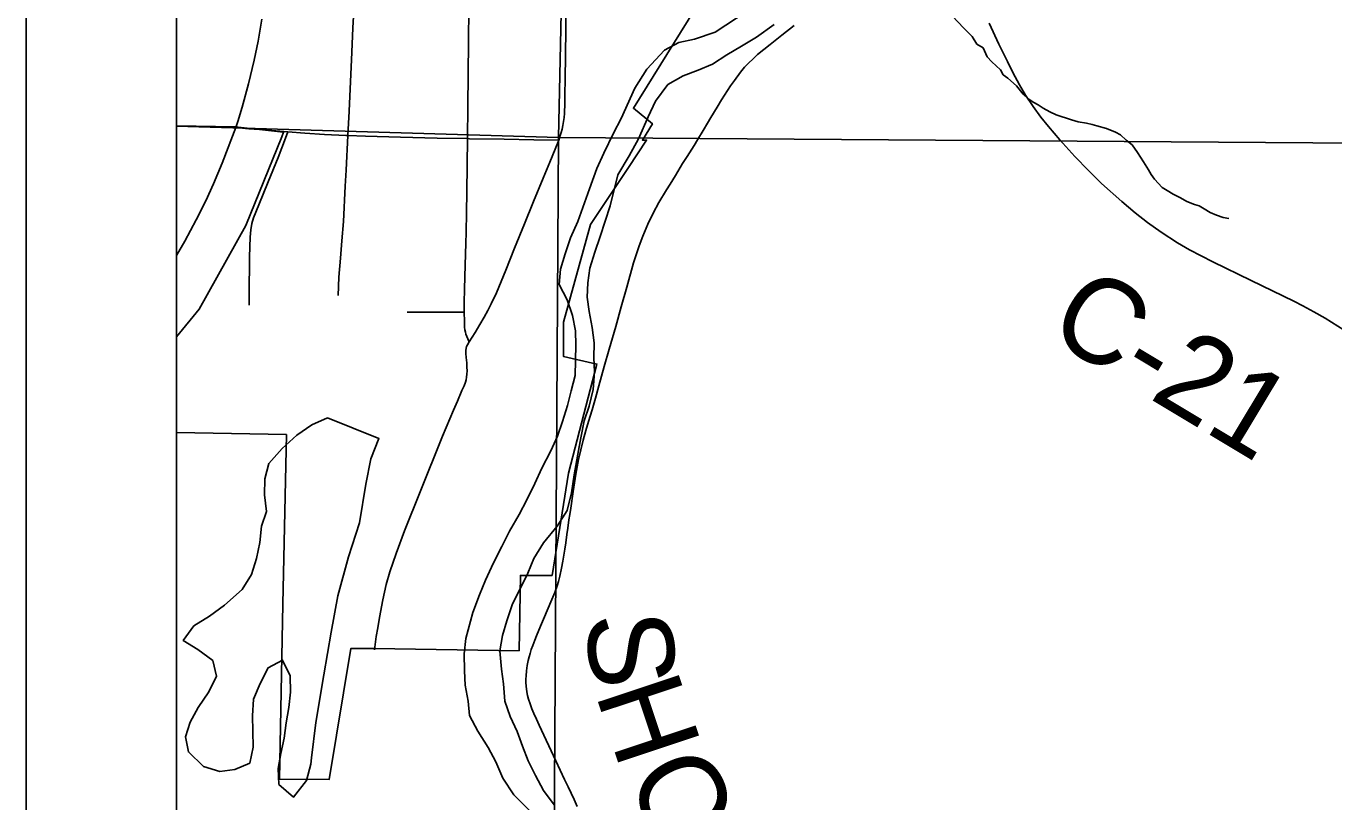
# Model space of a CAD drawing. Extents: x -8.8 to 41.4, y 0 to 34.6.
# Drawn here: x -8.774 to -7.904, y 16.161 to 16.678 of the extents above; entities that cross this region are included whole.
import ezdxf

# ---------------------------------------------------------------- set-up
doc = ezdxf.new("R2010")
doc.units = 0
for name, color, linetype in [('GM_X_City_Street', 7, 'Continuous'), ('GM_X_Corporation', 7, 'Continuous'), ('GM_X_County_Road', 7, 'Continuous'), ('GM_X_Major_Lake', 7, 'Continuous'), ('GM_X_Minor_River', 7, 'Continuous'), ('GM_X_Township_Road_Text', 7, 'Continuous'), ('GM_X_US_Route', 7, 'Continuous'), ('SH_Border', 7, 'Continuous')]:
    doc.layers.add(name, color=color, linetype=linetype)

msp = doc.modelspace()

# ---------------------------------------------------------------- linework, layer by layer
at = {"layer": 'GM_X_City_Street'}
for points in [[(-8.5667, 16.49846), (-8.56617, 16.51081), (-8.56514, 16.52326), (-8.56417, 16.53491), (-8.5631, 16.54775), (-8.56186, 16.5713), (-8.56129, 16.58184), (-8.56017, 16.60505), (-8.55938, 16.62117), (-8.55748, 16.6605), (-8.55678, 16.67663), (-8.55607, 16.69151), (-8.55316, 16.72915), (-8.5527, 16.73735), (-8.5517, 16.75531), (-8.54759, 16.82863), (-8.54694, 16.84339), (-8.54679, 16.84674)], [(-8.48719, 16.42822), (-8.4842, 16.43521), (-8.48281, 16.43844), (-8.48179, 16.44092), (-8.48135, 16.44244), (-8.4811, 16.44421), (-8.48091, 16.44618), (-8.48084, 16.4484), (-8.48091, 16.4508), (-8.48104, 16.45378), (-8.48133, 16.45726), (-8.48155, 16.4598), (-8.48155, 16.46195), (-8.48141, 16.46335), (-8.4811, 16.46449), (-8.48046, 16.46576), (-8.47946, 16.46765), (-8.47546, 16.47393), (-8.47235, 16.4792), (-8.46943, 16.48401), (-8.4669, 16.48858), (-8.46468, 16.49302), (-8.46131, 16.50025), (-8.45508, 16.51545), (-8.44925, 16.52995), (-8.44264, 16.54625), (-8.43665, 16.56106), (-8.43023, 16.57657), (-8.42574, 16.58737), (-8.42222, 16.59584), (-8.41984, 16.60189), (-8.41905, 16.60435), (-8.41822, 16.60693), (-8.41755, 16.60935), (-8.41697, 16.61177), (-8.41657, 16.61425), (-8.41622, 16.61694), (-8.41599, 16.61972), (-8.41572, 16.62645), (-8.41564, 16.63273), (-8.41554, 16.64203), (-8.41488, 16.69208)], [(-8.47946, 16.46765), (-8.48033, 16.46959), (-8.48097, 16.47121), (-8.48157, 16.47271), (-8.48196, 16.47412), (-8.48225, 16.47574), (-8.48246, 16.47745), (-8.48255, 16.47899), (-8.48264, 16.48129), (-8.48281, 16.4874), (-8.48272, 16.49359), (-8.48246, 16.50299), (-8.48202, 16.51872), (-8.48169, 16.5333), (-8.48152, 16.54053), (-8.4813, 16.55377), (-8.48107, 16.56738), (-8.48061, 16.60292), (-8.4803, 16.62437), (-8.47981, 16.66741), (-8.47966, 16.69004)], [(-8.63483, 16.61028), (-8.63241, 16.61007), (-8.62609, 16.60955), (-8.61907, 16.60896), (-8.60548, 16.60784), (-8.60008, 16.60739), (-8.58883, 16.60662), (-8.57576, 16.60578), (-8.56158, 16.6051), (-8.56017, 16.60505), (-8.54838, 16.60466), (-8.52509, 16.60389), (-8.50078, 16.60335), (-8.48061, 16.60292), (-8.47911, 16.60288), (-8.45617, 16.60252), (-8.4363, 16.60224), (-8.41984, 16.60189)], [(-8.62591, 16.49199), (-8.62592, 16.49882), (-8.6257, 16.52428), (-8.62527, 16.53733), (-8.62478, 16.54227), (-8.62398, 16.54654), (-8.62293, 16.55011), (-8.61953, 16.55878), (-8.61312, 16.57428), (-8.60647, 16.59035), (-8.60167, 16.60314), (-8.60008, 16.60739)], [(-8.5206, 16.48748), (-8.51286, 16.48747), (-8.50132, 16.48747), (-8.48992, 16.48746), (-8.48281, 16.4874)]]:
    msp.add_lwpolyline(points, dxfattribs=at)
at = {"layer": 'GM_X_Corporation'}
for points in [[(-8.6743, 18.69247), (-8.6743, 14.09996), (-5.44416, 14.09996), (-5.44317, 14.22654), (-5.4429, 14.26177), (-5.44035, 14.58818), (-5.43679, 15.04456), (-5.435, 15.31635), (-5.42821, 16.35067), (-5.4212, 16.54833), (-5.41292, 17.38361), (-5.40083, 18.63689)], [(-8.6743, 17.24471), (-8.6743, 16.61157), (-8.63507, 16.61081), (-8.60299, 16.60722), (-8.60422, 16.60416), (-8.62815, 16.54522), (-8.65907, 16.4894), (-8.6743, 16.47104), (-8.6743, 16.4073), (-8.60107, 16.40598), (-8.60337, 16.29312), (-8.60575, 16.17658), (-8.57266, 16.17628), (-8.5582, 16.26352), (-8.54271, 16.26348), (-8.4462, 16.26203), (-8.44534, 16.31218), (-8.42424, 16.31218), (-8.41328, 16.38015), (-8.39443, 16.45291), (-8.41674, 16.45798), (-8.41667, 16.48073), (-8.39862, 16.54582), (-8.37338, 16.58383), (-8.36135, 16.60196), (-8.36415, 16.60199), (-8.35743, 16.61288), (-8.37005, 16.62314), (-8.3024, 16.73229)]]:
    msp.add_lwpolyline(points, dxfattribs=at)
for points in [[(-8.6743, 17.6149), (-8.6743, 16.61123), (-8.42005, 16.60371), (-8.39835, 17.60863)], [(-8.39835, 17.60863), (-7.43777, 17.58688), (-7.44736, 16.59683), (-8.42005, 16.60371)], [(-8.6743, 16.61123), (-8.6743, 15.60235), (-8.42609, 15.59413), (-8.42005, 16.60371)], [(-8.42005, 16.60371), (-7.44736, 16.59683), (-7.4468, 15.57832), (-8.42609, 15.59413)]]:
    msp.add_lwpolyline(points, close=True, dxfattribs=at)
at = {"layer": 'GM_X_County_Road'}
for points in [[(-8.38957, 16.45116), (-8.38626, 16.46289), (-8.38188, 16.47778), (-8.37819, 16.49092), (-8.37453, 16.50408), (-8.36994, 16.52024), (-8.36632, 16.53151), (-8.36394, 16.53795), (-8.36053, 16.54601), (-8.35704, 16.55335), (-8.35308, 16.56043), (-8.34797, 16.56895), (-8.34571, 16.57265), (-8.34215, 16.57846), (-8.3406, 16.5811), (-8.33732, 16.58635), (-8.336, 16.58845), (-8.33433, 16.59106), (-8.3297, 16.59838), (-8.32742, 16.60206), (-8.3236, 16.60845), (-8.32075, 16.61325), (-8.31855, 16.61699), (-8.31438, 16.62392), (-8.31145, 16.62867), (-8.30539, 16.63813), (-8.30289, 16.6417), (-8.29876, 16.64722), (-8.29606, 16.6505), (-8.29383, 16.65288), (-8.29018, 16.65632), (-8.28742, 16.65889), (-8.27918, 16.66556), (-8.27139, 16.67174), (-8.26315, 16.67832)], [(-8.13335, 16.6799), (-8.12681, 16.66588), (-8.12105, 16.65421), (-8.11757, 16.64695), (-8.11318, 16.63878), (-8.10908, 16.63191), (-8.10398, 16.62423), (-8.09887, 16.6173), (-8.09384, 16.6111), (-8.08627, 16.60212), (-8.07629, 16.59111), (-8.06727, 16.58178), (-8.05844, 16.57312), (-8.04511, 16.56113), (-8.03611, 16.55358), (-8.02783, 16.54713), (-8.01879, 16.54066), (-8.00796, 16.53355), (-7.99992, 16.52894), (-7.98453, 16.52099), (-7.95892, 16.50849), (-7.93043, 16.49472), (-7.92444, 16.49158), (-7.91724, 16.48774), (-7.90968, 16.4834), (-7.897, 16.47551)], [(-8.41911, 16.31166), (-8.41797, 16.31694), (-8.41702, 16.32176), (-8.41579, 16.3297), (-8.41515, 16.33396), (-8.41442, 16.33946), (-8.41377, 16.34366), (-8.41306, 16.34909), (-8.41252, 16.35274), (-8.41185, 16.35697), (-8.41029, 16.36801), (-8.40852, 16.37968), (-8.4066, 16.38945), (-8.40353, 16.40215), (-8.40175, 16.40875), (-8.40072, 16.41233), (-8.39891, 16.41826), (-8.39759, 16.42238), (-8.39542, 16.43013), (-8.39306, 16.43846), (-8.38957, 16.45116)], [(-8.54252, 16.26263), (-8.54129, 16.27143), (-8.54028, 16.27734), (-8.53912, 16.28415), (-8.537, 16.29588), (-8.53462, 16.30613), (-8.53229, 16.31447), (-8.52811, 16.32679), (-8.52242, 16.3419), (-8.51214, 16.36791), (-8.49722, 16.40478), (-8.48977, 16.4222), (-8.48719, 16.42822)], [(-8.40746, 16.15843), (-8.40959, 16.16292), (-8.41353, 16.17135), (-8.4159, 16.17642), (-8.41885, 16.18258), (-8.42169, 16.18878), (-8.43277, 16.21243), (-8.43459, 16.21641), (-8.4364, 16.22037), (-8.43778, 16.22345), (-8.43893, 16.22678), (-8.43988, 16.22978), (-8.44055, 16.23225), (-8.441, 16.2347), (-8.44152, 16.23845), (-8.44173, 16.24098), (-8.44175, 16.24316), (-8.44157, 16.24541), (-8.44127, 16.24858), (-8.44074, 16.2522), (-8.44008, 16.25565), (-8.43953, 16.25806), (-8.43889, 16.26026), (-8.43814, 16.26278), (-8.43715, 16.26555), (-8.4358, 16.26901), (-8.43464, 16.27196), (-8.43203, 16.27841), (-8.42923, 16.28455), (-8.42496, 16.29467), (-8.4224, 16.30077), (-8.42088, 16.3053), (-8.41996, 16.30823), (-8.41911, 16.31166)]]:
    msp.add_lwpolyline(points, dxfattribs=at)
at = {"layer": 'GM_X_Major_Lake'}
for points in [[(-8.22704, 16.74464), (-8.23767, 16.73206), (-8.24979, 16.72028), (-8.25988, 16.71262), (-8.27113, 16.70461), (-8.28161, 16.69696), (-8.29169, 16.68967), (-8.30138, 16.68314), (-8.3157, 16.67371), (-8.32949, 16.66919), (-8.33981, 16.66685), (-8.34944, 16.66183), (-8.36121, 16.64929), (-8.36918, 16.63662), (-8.37815, 16.61639), (-8.38338, 16.60668), (-8.38987, 16.59321), (-8.39435, 16.5831), (-8.39932, 16.56958)], [(-8.31749, 16.65249), (-8.30782, 16.65865), (-8.29816, 16.66443), (-8.28811, 16.67058), (-8.27647, 16.67895)], [(-8.38558, 16.55821), (-8.38045, 16.57887), (-8.37285, 16.59155), (-8.36681, 16.60275), (-8.3603, 16.61736), (-8.35542, 16.62784), (-8.34711, 16.63898), (-8.33708, 16.64474), (-8.32709, 16.64861), (-8.31749, 16.65249)], [(-8.39932, 16.56958), (-8.40711, 16.54774), (-8.41195, 16.53686), (-8.41563, 16.52632), (-8.41854, 16.51614), (-8.41956, 16.50592), (-8.41412, 16.49553), (-8.41058, 16.48519), (-8.40856, 16.47489), (-8.40842, 16.46539), (-8.40892, 16.44528), (-8.41146, 16.43509), (-8.41398, 16.42529), (-8.41729, 16.41474), (-8.42057, 16.40495), (-8.42499, 16.39519), (-8.43098, 16.38357), (-8.4358, 16.37344), (-8.44101, 16.36256), (-8.44619, 16.35282), (-8.45255, 16.34159), (-8.45774, 16.33147), (-8.46333, 16.3206), (-8.46856, 16.30897), (-8.47261, 16.2992), (-8.47708, 16.28754), (-8.48169, 16.27019), (-8.48271, 16.25996), (-8.48261, 16.24857), (-8.48209, 16.23907), (-8.48008, 16.22839), (-8.47918, 16.21887), (-8.47374, 16.20848), (-8.46679, 16.19768), (-8.46171, 16.18806), (-8.45705, 16.17731), (-8.44973, 16.16612), (-8.43935, 16.1556)], [(-8.42293, 16.15937), (-8.4299, 16.16903), (-8.43535, 16.17904), (-8.44005, 16.18865), (-8.44398, 16.19862), (-8.44754, 16.20821), (-8.45222, 16.21819), (-8.45576, 16.22853), (-8.45662, 16.23995), (-8.45789, 16.24985), (-8.4591, 16.26203), (-8.45733, 16.27224), (-8.45442, 16.28203), (-8.45074, 16.29257), (-8.44034, 16.31357), (-8.43629, 16.32334), (-8.42995, 16.33381), (-8.42093, 16.34497), (-8.41421, 16.35543), (-8.41126, 16.36713), (-8.40944, 16.37923), (-8.4072, 16.39284), (-8.40502, 16.4038), (-8.40284, 16.41513), (-8.39956, 16.42492), (-8.397, 16.43587), (-8.39595, 16.44761), (-8.39647, 16.45712), (-8.39622, 16.46698), (-8.39749, 16.47726), (-8.3995, 16.48795), (-8.40078, 16.49747), (-8.40054, 16.50696), (-8.39915, 16.51679), (-8.39585, 16.52734), (-8.39217, 16.53788), (-8.38558, 16.55821)]]:
    msp.add_lwpolyline(points, dxfattribs=at)
at = {"layer": 'GM_X_Minor_River'}
for points in [[(-8.15792, 16.68471), (-8.15023, 16.67646), (-8.14472, 16.67095), (-8.14147, 16.66589), (-8.13738, 16.66347), (-8.13455, 16.65729), (-8.13162, 16.65415), (-8.12573, 16.64863), (-8.12394, 16.64552), (-8.12098, 16.64314), (-8.11508, 16.63799), (-8.11071, 16.63252), (-8.1074, 16.62937), (-8.10368, 16.62696), (-8.1007, 16.62534), (-8.09734, 16.62332), (-8.09287, 16.62088), (-8.08876, 16.61884), (-8.07861, 16.61545), (-8.07409, 16.61415), (-8.06842, 16.61319), (-8.06465, 16.6123), (-8.06164, 16.61144), (-8.05524, 16.60969), (-8.04924, 16.6072), (-8.04588, 16.60556), (-8.0422, 16.60202), (-8.03813, 16.59884), (-8.0345, 16.59377), (-8.03054, 16.58755), (-8.02731, 16.58212), (-8.02552, 16.57902), (-8.02335, 16.5759), (-8.01822, 16.5704), (-8.01487, 16.56839), (-8.01077, 16.56596), (-8.00591, 16.56352), (-8.00181, 16.56109), (-7.99656, 16.55901), (-7.99355, 16.55815), (-7.9902, 16.55613), (-7.9861, 16.55371), (-7.98198, 16.55204), (-7.97748, 16.55037), (-7.97369, 16.54985)], [(-8.57374, 16.41716), (-8.58411, 16.41249), (-8.59417, 16.40553), (-8.60388, 16.39666), (-8.61287, 16.38664), (-8.61541, 16.37645), (-8.61567, 16.36583), (-8.61443, 16.35478), (-8.61772, 16.345), (-8.61875, 16.33401), (-8.62091, 16.32344), (-8.62422, 16.31289), (-8.63055, 16.3028), (-8.6422, 16.29246), (-8.65227, 16.28512), (-8.66269, 16.27855), (-8.66977, 16.26886), (-8.66004, 16.26292), (-8.64997, 16.25545), (-8.64757, 16.24514), (-8.65277, 16.23464), (-8.65987, 16.22419), (-8.66506, 16.21445), (-8.66834, 16.20466), (-8.66631, 16.19474), (-8.6563, 16.18499), (-8.64536, 16.18168), (-8.63545, 16.18295), (-8.62547, 16.18725), (-8.6233, 16.19783), (-8.62342, 16.20846), (-8.62354, 16.21871), (-8.62288, 16.22971), (-8.61844, 16.24023), (-8.61324, 16.25073), (-8.60362, 16.2558), (-8.59856, 16.24542), (-8.59845, 16.23441), (-8.59947, 16.22418), (-8.60125, 16.21398), (-8.60264, 16.20376), (-8.6048, 16.19356), (-8.60656, 16.18374), (-8.60607, 16.17309), (-8.59641, 16.1645), (-8.58777, 16.17567), (-8.58484, 16.1866)], [(-8.58484, 16.1866), (-8.58435, 16.19077), (-8.58148, 16.21424), (-8.57613, 16.24599), (-8.57124, 16.27435), (-8.56684, 16.29853), (-8.55973, 16.32455), (-8.55232, 16.34715), (-8.54826, 16.37286), (-8.54479, 16.38986), (-8.53952, 16.40339), (-8.57374, 16.41716)]]:
    msp.add_lwpolyline(points, dxfattribs=at)
at = {"layer": 'GM_X_US_Route'}
for points in [[(-8.63483, 16.61028), (-8.63336, 16.61441), (-8.63046, 16.62388), (-8.62629, 16.63944), (-8.62251, 16.65511), (-8.61987, 16.66786), (-8.61736, 16.68252)], [(-8.6743, 16.52518), (-8.66877, 16.53466), (-8.66108, 16.54883), (-8.65468, 16.56156), (-8.64953, 16.57283), (-8.64378, 16.58655), (-8.63689, 16.6045), (-8.63483, 16.61028)]]:
    msp.add_lwpolyline(points, dxfattribs=at)
at = {"layer": 'SH_Border'}
for p, q in [((-8.7743, 20.99996), (-8.7743, 13.99996)), ((-8.6743, 20.89996), (-8.6743, 14.09996))]:
    msp.add_line(p, q, dxfattribs=at)

# ---------------------------------------------------------------- texts
at = {"layer": 'GM_X_Township_Road_Text'}
for s, height, rotation, p in [('C-21', 0.056818, 328.97717, (-8.09639, 16.47184)), ('S', 0.05682, 275.64914, (-8.40235, 16.28546)), ('H', 0.05682, 288.42982, (-8.3957, 16.23381)), ('O', 0.05682, 297.74069, (-8.37594, 16.17711))]:
    msp.add_text(s, height=height, rotation=rotation, dxfattribs=at).set_placement(p)

doc.saveas('drawing.dxf')
